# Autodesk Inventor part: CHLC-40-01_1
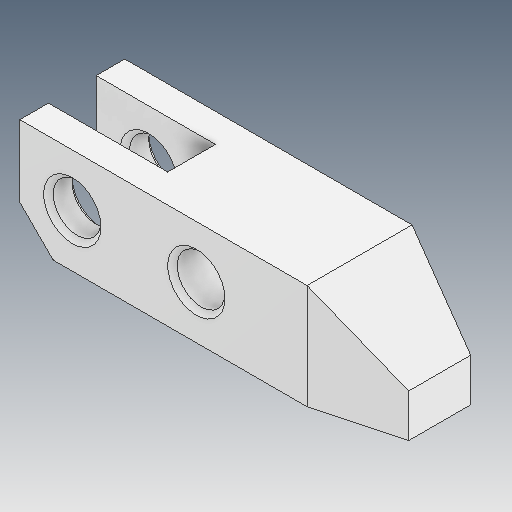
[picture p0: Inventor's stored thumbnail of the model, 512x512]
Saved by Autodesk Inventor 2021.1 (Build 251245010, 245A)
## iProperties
Created: 2021-05
Part Number: CHLC-40-01_1
Material: Ogólny
Document SubType Name: Modeling
Designer: user
Density: 1 g/cm^3
Appearance: Domyślna
Author: user
Revision Number: ÈÎºÎ
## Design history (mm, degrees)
feature "ÊäÈë1"
node "Bryła1"
